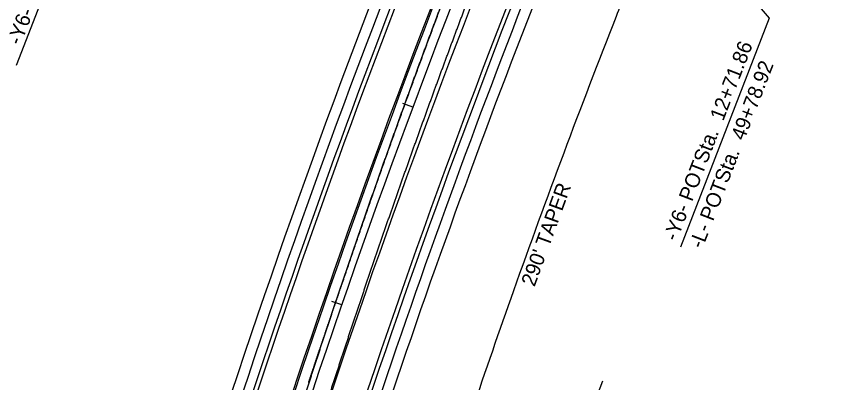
# Model space of a CAD drawing. Extents: x 1974386 to 1979988, y 776712 to 784860.
# Drawn here: x 1977461.3 to 1977853.8, y 781517 to 781691.1 of the extents above; entities that cross this region are included whole.
import ezdxf

# ---------------------------------------------------------------- set-up
doc = ezdxf.new("R2010")
doc.units = 0
for name, color, linetype in [('Prop Conc 2ft 6in Curb and Gutter', 7, 'Continuous'), ('Prop Conc 4in Sidewalk', 7, 'Continuous'), ('Prop Conc 5in Monolithic Keyed In Island', 7, 'Continuous'), ('Prop Dimension', 7, 'Continuous'), ('Prop EOT', 7, 'Continuous'), ('Prop Horizontal Alignment', 7, 'Continuous'), ('Prop Horizontal Alignment Station Label', 7, 'Continuous'), ('Prop Horizontal Alignment Tick Small', 7, 'Continuous'), ('Prop Lane Lines', 7, 'Continuous')]:
    doc.layers.add(name, color=color, linetype=linetype)

msp = doc.modelspace()

# ---------------------------------------------------------------- linework, layer by layer
at = {"layer": 'Prop Conc 2ft 6in Curb and Gutter'}
for radius, start, end in [(4173.25, 154.30709, 162.22085), (4226.75, 157.96844, 161.65559)]:
    msp.add_arc((1981585.24, 780180.82), radius, start, end, dxfattribs=at)
at = {"layer": 'Prop Conc 4in Sidewalk'}
for radius, start in [(4168.75, 156.07574), (4163.75, 156.07574), (4236.25, 157.96844), (4231.25, 157.97234)]:
    msp.add_arc((1981585.24, 780180.82), radius, start, 162.22085, dxfattribs=at)
at = {"layer": 'Prop Conc 5in Monolithic Keyed In Island'}
msp.add_arc((1981585.24, 780180.82), 4208, 157.44193, 162.14647, dxfattribs=at)
for points in [[(1977681.22, 781743.09), (1977680.6, 781741.49), (1977680.29, 781740.69), (1977679.98, 781739.89), (1977679.67, 781739.09), (1977679.36, 781738.29), (1977679.05, 781737.49), (1977678.74, 781736.7), (1977678.43, 781735.9), (1977678.12, 781735.1), (1977677.81, 781734.3), (1977677.5, 781733.5), (1977677.19, 781732.7), (1977676.88, 781731.9), (1977676.58, 781731.1), (1977676.27, 781730.3), (1977675.96, 781729.5), (1977675.65, 781728.7), (1977675.34, 781727.9), (1977675.04, 781727.1), (1977674.73, 781726.3), (1977674.42, 781725.5), (1977674.11, 781724.7), (1977673.81, 781723.9), (1977673.5, 781723.1), (1977673.19, 781722.3), (1977672.89, 781721.5), (1977672.58, 781720.7), (1977672.28, 781719.9), (1977671.97, 781719.1), (1977671.66, 781718.3), (1977671.36, 781717.5), (1977671.05, 781716.7), (1977670.75, 781715.9), (1977670.44, 781715.1), (1977670.14, 781714.3), (1977669.83, 781713.5), (1977669.53, 781712.7), (1977669.22, 781711.9), (1977668.92, 781711.09), (1977668.61, 781710.29), (1977668.31, 781709.49), (1977668.01, 781708.69), (1977667.7, 781707.89), (1977667.4, 781707.09), (1977667.1, 781706.29), (1977666.79, 781705.49), (1977666.49, 781704.68), (1977666.19, 781703.88), (1977665.88, 781703.08), (1977665.58, 781702.28), (1977665.28, 781701.48), (1977664.98, 781700.68), (1977664.67, 781699.87), (1977664.37, 781699.07), (1977664.07, 781698.27), (1977663.77, 781697.47), (1977663.47, 781696.67), (1977663.17, 781695.86), (1977662.87, 781695.06), (1977662.56, 781694.26), (1977662.26, 781693.46), (1977661.96, 781692.66), (1977661.66, 781691.85), (1977661.36, 781691.05), (1977661.06, 781690.25), (1977660.76, 781689.45), (1977660.46, 781688.64), (1977660.16, 781687.84), (1977659.86, 781687.04), (1977659.56, 781686.23), (1977659.27, 781685.43), (1977658.97, 781684.63), (1977658.67, 781683.83)], [(1977658.67, 781683.83), (1977658.37, 781683.02), (1977658.07, 781682.22), (1977657.77, 781681.42), (1977657.47, 781680.61), (1977657.18, 781679.81), (1977656.88, 781679.01), (1977656.58, 781678.2), (1977656.28, 781677.4), (1977655.99, 781676.6), (1977655.69, 781675.79), (1977655.39, 781674.99), (1977655.1, 781674.19), (1977654.8, 781673.38), (1977654.5, 781672.58), (1977654.21, 781671.77), (1977653.91, 781670.97), (1977653.61, 781670.17), (1977653.32, 781669.36), (1977653.02, 781668.56), (1977652.73, 781667.75), (1977652.43, 781666.95), (1977652.14, 781666.14), (1977651.84, 781665.34), (1977651.55, 781664.54), (1977651.25, 781663.73), (1977650.96, 781662.93), (1977650.66, 781662.12), (1977650.37, 781661.32), (1977650.07, 781660.51), (1977649.78, 781659.71), (1977649.49, 781658.9), (1977649.19, 781658.1), (1977648.9, 781657.29), (1977648.61, 781656.49), (1977648.31, 781655.68), (1977648.02, 781654.88), (1977647.73, 781654.07), (1977647.44, 781653.27), (1977647.14, 781652.46), (1977646.85, 781651.66), (1977646.56, 781650.85), (1977646.27, 781650.05), (1977645.98, 781649.24), (1977645.68, 781648.44), (1977645.39, 781647.63), (1977645.1, 781646.82), (1977644.81, 781646.02), (1977644.52, 781645.21), (1977644.23, 781644.41), (1977643.94, 781643.6), (1977643.65, 781642.79), (1977643.36, 781641.99), (1977643.07, 781641.18), (1977642.78, 781640.38), (1977642.49, 781639.57), (1977642.2, 781638.76), (1977641.91, 781637.96), (1977641.62, 781637.15), (1977641.33, 781636.34), (1977641.04, 781635.54), (1977640.75, 781634.73), (1977640.46, 781633.92), (1977640.18, 781633.12), (1977639.89, 781632.31), (1977639.6, 781631.5), (1977639.31, 781630.7), (1977639.02, 781629.89), (1977638.74, 781629.08), (1977638.45, 781628.28), (1977638.16, 781627.47), (1977637.88, 781626.66), (1977637.59, 781625.86), (1977637.3, 781625.05), (1977637.01, 781624.24)], [(1977637.01, 781624.24), (1977636.73, 781623.43), (1977636.44, 781622.63), (1977636.16, 781621.82), (1977635.87, 781621.01), (1977635.58, 781620.2), (1977635.3, 781619.4), (1977635.01, 781618.59), (1977634.73, 781617.78), (1977634.44, 781616.97), (1977634.16, 781616.16), (1977633.87, 781615.36), (1977633.59, 781614.55), (1977633.3, 781613.74), (1977633.02, 781612.93), (1977632.74, 781612.12), (1977632.45, 781611.32), (1977632.17, 781610.51), (1977631.88, 781609.7), (1977631.6, 781608.89), (1977631.32, 781608.08), (1977631.03, 781607.27), (1977630.75, 781606.47), (1977630.47, 781605.66), (1977630.19, 781604.85), (1977629.9, 781604.04), (1977629.62, 781603.23), (1977629.34, 781602.42), (1977629.06, 781601.61), (1977628.78, 781600.8), (1977628.49, 781600), (1977628.21, 781599.19), (1977627.93, 781598.38), (1977627.65, 781597.57), (1977627.37, 781596.76), (1977627.09, 781595.95), (1977626.81, 781595.14), (1977626.53, 781594.33), (1977626.25, 781593.52), (1977625.97, 781592.71), (1977625.69, 781591.9), (1977625.41, 781591.09), (1977625.13, 781590.28), (1977624.85, 781589.47), (1977624.57, 781588.66), (1977624.29, 781587.85), (1977624.01, 781587.04), (1977623.73, 781586.23), (1977623.45, 781585.42), (1977623.17, 781584.61), (1977622.9, 781583.8), (1977622.62, 781582.99), (1977622.34, 781582.18), (1977622.06, 781581.37), (1977621.78, 781580.56), (1977621.51, 781579.75), (1977621.23, 781578.94), (1977620.95, 781578.13), (1977620.68, 781577.32), (1977620.4, 781576.51), (1977620.12, 781575.7), (1977619.85, 781574.89), (1977619.57, 781574.08), (1977619.29, 781573.27), (1977619.02, 781572.46), (1977618.74, 781571.65), (1977618.47, 781570.83), (1977618.19, 781570.02), (1977617.91, 781569.21), (1977617.64, 781568.4), (1977617.36, 781567.59), (1977617.09, 781566.78), (1977616.81, 781565.97), (1977616.54, 781565.16), (1977616.27, 781564.34)], [(1977616.27, 781564.34), (1977615.82, 781563.07), (1977615.6, 781562.43), (1977615.38, 781561.79), (1977615.16, 781561.15), (1977614.94, 781560.51), (1977614.72, 781559.87), (1977614.5, 781559.23), (1977614.28, 781558.59), (1977614.06, 781557.95), (1977613.84, 781557.31), (1977613.62, 781556.67), (1977613.4, 781556.04), (1977613.18, 781555.4), (1977612.96, 781554.76), (1977612.74, 781554.12), (1977612.52, 781553.48), (1977612.3, 781552.84), (1977612.08, 781552.2), (1977611.86, 781551.56), (1977611.64, 781550.92), (1977611.42, 781550.28), (1977611.2, 781549.64), (1977610.98, 781549), (1977610.77, 781548.36), (1977610.55, 781547.72), (1977610.33, 781547.08), (1977610.11, 781546.44), (1977609.89, 781545.8), (1977609.67, 781545.16), (1977609.45, 781544.52), (1977609.24, 781543.88), (1977609.02, 781543.24), (1977608.8, 781542.6), (1977608.58, 781541.96), (1977608.37, 781541.32), (1977608.15, 781540.68), (1977607.93, 781540.04), (1977607.71, 781539.4), (1977607.5, 781538.76), (1977607.28, 781538.12), (1977607.06, 781537.48), (1977606.84, 781536.84), (1977606.63, 781536.2), (1977606.41, 781535.56), (1977606.19, 781534.92), (1977605.98, 781534.28), (1977605.76, 781533.63), (1977605.55, 781532.99), (1977605.33, 781532.35), (1977605.11, 781531.71), (1977604.9, 781531.07), (1977604.68, 781530.43), (1977604.47, 781529.79), (1977604.25, 781529.15), (1977604.03, 781528.51), (1977603.82, 781527.87), (1977603.6, 781527.23), (1977603.39, 781526.59), (1977603.17, 781525.94), (1977602.96, 781525.3), (1977602.74, 781524.66), (1977602.53, 781524.02), (1977602.31, 781523.38), (1977602.1, 781522.74), (1977601.88, 781522.1), (1977601.67, 781521.46), (1977601.45, 781520.82), (1977601.24, 781520.17), (1977601.03, 781519.53), (1977600.81, 781518.89), (1977600.6, 781518.25), (1977600.38, 781517.61), (1977600.17, 781516.97)]]:
    msp.add_spline(points, degree=3, dxfattribs=at)
at = {"layer": 'Prop Dimension'}
for centre, radius, start, end in [((1982594.42, 779780.37), 5210.83, 158.22493, 158.48863), ((1981701.08, 780137.49), 4248.77, 158.5515, 160.43084), ((1981585.24, 780180.82), 4125.1, 160.45901, 162.14498)]:
    msp.add_arc(centre, radius, start, end, dxfattribs=at)
at = {"layer": 'Prop EOT'}
for centre, radius, start, end in [((1981585.79, 780180.59), 4175.85, 153.34433, 162.22022), ((1981585.24, 780180.82), 4208.75, 157.44193, 162.22085), ((1981585.24, 780180.82), 4224.75, 157.96844, 161.65559)]:
    msp.add_arc(centre, radius, start, end, dxfattribs=at)
for points in [[(1977655.48, 781675.22), (1977655.82, 781676.14), (1977656.16, 781677.06), (1977656.5, 781677.98), (1977656.84, 781678.9), (1977657.18, 781679.82), (1977657.52, 781680.74), (1977657.86, 781681.66), (1977658.2, 781682.58), (1977658.55, 781683.5), (1977658.89, 781684.42), (1977659.23, 781685.34), (1977659.57, 781686.26), (1977659.92, 781687.17), (1977660.26, 781688.09), (1977660.6, 781689.01), (1977660.94, 781689.93), (1977661.29, 781690.85), (1977661.63, 781691.77), (1977661.98, 781692.69), (1977662.32, 781693.61), (1977662.66, 781694.52), (1977663.01, 781695.44), (1977663.35, 781696.36), (1977663.7, 781697.28), (1977664.04, 781698.2), (1977664.39, 781699.11), (1977664.73, 781700.03), (1977665.08, 781700.95), (1977665.43, 781701.87), (1977665.77, 781702.79), (1977666.12, 781703.7), (1977666.47, 781704.62), (1977666.81, 781705.54), (1977667.16, 781706.46), (1977667.51, 781707.37), (1977667.85, 781708.29), (1977668.2, 781709.21), (1977668.55, 781710.12), (1977668.9, 781711.04), (1977669.25, 781711.96), (1977669.6, 781712.88), (1977669.94, 781713.79), (1977670.29, 781714.71), (1977670.64, 781715.63), (1977670.99, 781716.54), (1977671.34, 781717.46), (1977671.69, 781718.37), (1977672.04, 781719.29), (1977672.39, 781720.21), (1977672.74, 781721.12), (1977673.09, 781722.04), (1977673.44, 781722.96), (1977673.8, 781723.87), (1977674.15, 781724.79), (1977674.5, 781725.7), (1977674.85, 781726.62), (1977675.2, 781727.53), (1977675.55, 781728.45), (1977675.91, 781729.36), (1977676.26, 781730.28), (1977676.61, 781731.2), (1977676.97, 781732.11), (1977677.32, 781733.03), (1977677.67, 781733.94), (1977678.03, 781734.86), (1977678.38, 781735.77), (1977678.73, 781736.68), (1977679.09, 781737.6), (1977679.44, 781738.51), (1977679.8, 781739.43), (1977680.15, 781740.34), (1977680.51, 781741.26), (1977681.22, 781743.09)], [(1977630.92, 781606.93), (1977631.24, 781607.86), (1977631.56, 781608.78), (1977631.89, 781609.71), (1977632.21, 781610.64), (1977632.54, 781611.56), (1977632.86, 781612.49), (1977633.19, 781613.41), (1977633.51, 781614.34), (1977633.84, 781615.26), (1977634.17, 781616.19), (1977634.49, 781617.11), (1977634.82, 781618.04), (1977635.14, 781618.96), (1977635.47, 781619.88), (1977635.8, 781620.81), (1977636.13, 781621.73), (1977636.45, 781622.66), (1977636.78, 781623.58), (1977637.11, 781624.51), (1977637.44, 781625.43), (1977637.77, 781626.35), (1977638.09, 781627.28), (1977638.42, 781628.2), (1977638.75, 781629.13), (1977639.08, 781630.05), (1977639.41, 781630.97), (1977639.74, 781631.9), (1977640.07, 781632.82), (1977640.4, 781633.74), (1977640.73, 781634.67), (1977641.06, 781635.59), (1977641.39, 781636.51), (1977641.72, 781637.44), (1977642.05, 781638.36), (1977642.39, 781639.28), (1977642.72, 781640.21), (1977643.05, 781641.13), (1977643.38, 781642.05), (1977643.71, 781642.97), (1977644.05, 781643.9), (1977644.38, 781644.82), (1977644.71, 781645.74), (1977645.04, 781646.66), (1977645.38, 781647.59), (1977645.71, 781648.51), (1977646.05, 781649.43), (1977646.38, 781650.35), (1977646.71, 781651.28), (1977647.05, 781652.2), (1977647.38, 781653.12), (1977647.72, 781654.04), (1977648.05, 781654.96), (1977648.39, 781655.88), (1977648.72, 781656.81), (1977649.06, 781657.73), (1977649.39, 781658.65), (1977649.73, 781659.57), (1977650.07, 781660.49), (1977650.4, 781661.41), (1977650.74, 781662.33), (1977651.08, 781663.25), (1977651.41, 781664.18), (1977651.75, 781665.1), (1977652.09, 781666.02), (1977652.43, 781666.94), (1977652.77, 781667.86), (1977653.1, 781668.78), (1977653.44, 781669.7), (1977653.78, 781670.62), (1977654.12, 781671.54), (1977654.46, 781672.46), (1977654.8, 781673.38), (1977655.14, 781674.3), (1977655.48, 781675.22)], [(1977607.54, 781538.24), (1977607.85, 781539.17), (1977608.16, 781540.11), (1977608.46, 781541.04), (1977608.77, 781541.97), (1977609.08, 781542.9), (1977609.39, 781543.83), (1977609.7, 781544.76), (1977610.01, 781545.69), (1977610.32, 781546.62), (1977610.63, 781547.55), (1977610.94, 781548.48), (1977611.25, 781549.41), (1977611.56, 781550.34), (1977611.87, 781551.27), (1977612.18, 781552.2), (1977612.49, 781553.13), (1977612.8, 781554.06), (1977613.12, 781554.99), (1977613.43, 781555.92), (1977613.74, 781556.85), (1977614.05, 781557.78), (1977614.36, 781558.71), (1977614.68, 781559.64), (1977614.99, 781560.56), (1977615.3, 781561.49), (1977615.62, 781562.42), (1977615.93, 781563.35), (1977616.24, 781564.28), (1977616.56, 781565.21), (1977616.87, 781566.14), (1977617.19, 781567.07), (1977617.5, 781568), (1977617.82, 781568.92), (1977618.13, 781569.85), (1977618.45, 781570.78), (1977618.76, 781571.71), (1977619.08, 781572.64), (1977619.39, 781573.57), (1977619.71, 781574.49), (1977620.03, 781575.42), (1977620.34, 781576.35), (1977620.66, 781577.28), (1977620.98, 781578.21), (1977621.3, 781579.13), (1977621.61, 781580.06), (1977621.93, 781580.99), (1977622.25, 781581.92), (1977622.57, 781582.84), (1977622.88, 781583.77), (1977623.2, 781584.7), (1977623.52, 781585.63), (1977623.84, 781586.55), (1977624.16, 781587.48), (1977624.48, 781588.41), (1977624.8, 781589.33), (1977625.12, 781590.26), (1977625.44, 781591.19), (1977625.76, 781592.12), (1977626.08, 781593.04), (1977626.4, 781593.97), (1977626.72, 781594.9), (1977627.04, 781595.82), (1977627.37, 781596.75), (1977627.69, 781597.67), (1977628.01, 781598.6), (1977628.33, 781599.53), (1977628.65, 781600.45), (1977628.98, 781601.38), (1977629.3, 781602.3), (1977629.62, 781603.23), (1977629.94, 781604.16), (1977630.27, 781605.08), (1977630.59, 781606.01), (1977630.92, 781606.93)], [(1977585.36, 781469.17), (1977585.65, 781470.11), (1977585.94, 781471.04), (1977586.23, 781471.98), (1977586.52, 781472.91), (1977586.82, 781473.85), (1977587.11, 781474.79), (1977587.4, 781475.72), (1977587.7, 781476.66), (1977587.99, 781477.59), (1977588.28, 781478.53), (1977588.58, 781479.46), (1977588.87, 781480.4), (1977589.17, 781481.33), (1977589.46, 781482.27), (1977589.76, 781483.2), (1977590.05, 781484.14), (1977590.35, 781485.07), (1977590.64, 781486.01), (1977590.94, 781486.94), (1977591.23, 781487.88), (1977591.53, 781488.81), (1977591.83, 781489.74), (1977592.12, 781490.68), (1977592.42, 781491.61), (1977592.72, 781492.55), (1977593.01, 781493.48), (1977593.31, 781494.42), (1977593.61, 781495.35), (1977593.91, 781496.28), (1977594.2, 781497.22), (1977594.5, 781498.15), (1977594.8, 781499.09), (1977595.1, 781500.02), (1977595.4, 781500.95), (1977595.7, 781501.89), (1977596, 781502.82), (1977596.3, 781503.75), (1977596.6, 781504.69), (1977596.9, 781505.62), (1977597.2, 781506.55), (1977597.5, 781507.49), (1977597.8, 781508.42), (1977598.1, 781509.35), (1977598.4, 781510.29), (1977598.7, 781511.22), (1977599, 781512.15), (1977599.31, 781513.08), (1977599.61, 781514.02), (1977599.91, 781514.95), (1977600.21, 781515.88), (1977600.52, 781516.82), (1977600.82, 781517.75), (1977601.12, 781518.68), (1977601.43, 781519.61), (1977601.73, 781520.54), (1977602.03, 781521.48), (1977602.34, 781522.41), (1977602.64, 781523.34), (1977602.95, 781524.27), (1977603.25, 781525.2), (1977603.56, 781526.14), (1977603.86, 781527.07), (1977604.17, 781528), (1977604.47, 781528.93), (1977604.78, 781529.86), (1977605.08, 781530.79), (1977605.39, 781531.73), (1977605.7, 781532.66), (1977606, 781533.59), (1977606.31, 781534.52), (1977606.62, 781535.45), (1977606.92, 781536.38), (1977607.23, 781537.31), (1977607.54, 781538.24)]]:
    msp.add_spline(points, degree=3, dxfattribs=at)
at = {"layer": 'Prop Horizontal Alignment'}
msp.add_arc((1981585.24, 780180.82), 4200, 153.11985, 162.22085, dxfattribs=at)
at = {"layer": 'Prop Horizontal Alignment Station Label'}
for p, q in [((1977716.83, 781813.07), (1977819.32, 781690.28)), ((1977461.4, 781667.9), (1977502.75, 781775.73)), ((1977819.32, 781690.28), (1977777.24, 781581.35)), ((1977702.77, 781420.6), (1977740.26, 781517.77))]:
    msp.add_line(p, q, dxfattribs=at)
at = {"layer": 'Prop Horizontal Alignment Tick Small'}
for p, q in [((1977649.82, 781647.95), (1977645.13, 781649.7)), ((1977616.01, 781553.85), (1977611.28, 781555.48))]:
    msp.add_line(p, q, dxfattribs=at)
at = {"layer": 'Prop Lane Lines'}
msp.add_arc((1981585.24, 780180.82), 4191.25, 158.03179, 162.22085, dxfattribs=at)
for points in [[(1977665.76, 781671.31), (1977666.1, 781672.23), (1977666.44, 781673.15), (1977666.78, 781674.06), (1977667.12, 781674.98), (1977667.46, 781675.9), (1977667.8, 781676.82), (1977668.14, 781677.73), (1977668.48, 781678.65), (1977668.82, 781679.57), (1977669.16, 781680.48), (1977669.5, 781681.4), (1977669.84, 781682.32), (1977670.19, 781683.23), (1977670.53, 781684.15), (1977670.87, 781685.07), (1977671.21, 781685.98), (1977671.55, 781686.9), (1977671.9, 781687.82), (1977672.24, 781688.73), (1977672.58, 781689.65), (1977672.93, 781690.56), (1977673.27, 781691.48), (1977673.61, 781692.4), (1977673.96, 781693.31), (1977674.3, 781694.23), (1977674.65, 781695.14), (1977674.99, 781696.06), (1977675.34, 781696.97), (1977675.68, 781697.89), (1977676.03, 781698.8), (1977676.37, 781699.72), (1977676.72, 781700.63), (1977677.06, 781701.55), (1977677.41, 781702.46), (1977677.76, 781703.38), (1977678.1, 781704.29), (1977678.45, 781705.21), (1977678.8, 781706.12), (1977679.14, 781707.04), (1977679.49, 781707.95), (1977679.84, 781708.87), (1977680.19, 781709.78), (1977680.54, 781710.7), (1977680.88, 781711.61), (1977681.23, 781712.52), (1977681.58, 781713.44), (1977681.93, 781714.35), (1977682.28, 781715.27), (1977682.63, 781716.18), (1977682.98, 781717.09), (1977683.33, 781718.01), (1977683.68, 781718.92), (1977684.03, 781719.83), (1977684.38, 781720.75), (1977684.73, 781721.66), (1977685.08, 781722.57), (1977685.43, 781723.49), (1977685.78, 781724.4), (1977686.13, 781725.31), (1977686.49, 781726.23), (1977686.84, 781727.14), (1977687.19, 781728.05), (1977687.54, 781728.96), (1977687.9, 781729.88), (1977688.25, 781730.79), (1977688.6, 781731.7), (1977688.95, 781732.61), (1977689.31, 781733.53), (1977689.66, 781734.44), (1977690.02, 781735.35), (1977690.37, 781736.26), (1977690.72, 781737.18), (1977691.43, 781739)], [(1977641.26, 781603.2), (1977641.59, 781604.13), (1977641.91, 781605.05), (1977642.23, 781605.97), (1977642.56, 781606.89), (1977642.88, 781607.82), (1977643.21, 781608.74), (1977643.53, 781609.66), (1977643.85, 781610.58), (1977644.18, 781611.51), (1977644.5, 781612.43), (1977644.83, 781613.35), (1977645.16, 781614.27), (1977645.48, 781615.2), (1977645.81, 781616.12), (1977646.13, 781617.04), (1977646.46, 781617.96), (1977646.79, 781618.88), (1977647.11, 781619.81), (1977647.44, 781620.73), (1977647.77, 781621.65), (1977648.09, 781622.57), (1977648.42, 781623.49), (1977648.75, 781624.42), (1977649.08, 781625.34), (1977649.41, 781626.26), (1977649.74, 781627.18), (1977650.06, 781628.1), (1977650.39, 781629.02), (1977650.72, 781629.94), (1977651.05, 781630.86), (1977651.38, 781631.78), (1977651.71, 781632.71), (1977652.04, 781633.63), (1977652.37, 781634.55), (1977652.7, 781635.47), (1977653.03, 781636.39), (1977653.36, 781637.31), (1977653.7, 781638.23), (1977654.03, 781639.15), (1977654.36, 781640.07), (1977654.69, 781640.99), (1977655.02, 781641.91), (1977655.35, 781642.83), (1977655.69, 781643.75), (1977656.02, 781644.67), (1977656.35, 781645.59), (1977656.69, 781646.51), (1977657.02, 781647.43), (1977657.35, 781648.35), (1977657.69, 781649.27), (1977658.02, 781650.19), (1977658.35, 781651.11), (1977658.69, 781652.03), (1977659.02, 781652.94), (1977659.36, 781653.86), (1977659.69, 781654.78), (1977660.03, 781655.7), (1977660.36, 781656.62), (1977660.7, 781657.54), (1977661.03, 781658.46), (1977661.37, 781659.38), (1977661.71, 781660.29), (1977662.04, 781661.21), (1977662.38, 781662.13), (1977662.72, 781663.05), (1977663.05, 781663.97), (1977663.39, 781664.89), (1977663.73, 781665.8), (1977664.07, 781666.72), (1977664.41, 781667.64), (1977664.74, 781668.56), (1977665.08, 781669.48), (1977665.42, 781670.39), (1977665.76, 781671.31)], [(1977617.95, 781534.69), (1977618.26, 781535.62), (1977618.56, 781536.55), (1977618.87, 781537.48), (1977619.18, 781538.4), (1977619.49, 781539.33), (1977619.8, 781540.26), (1977620.1, 781541.19), (1977620.41, 781542.12), (1977620.72, 781543.04), (1977621.03, 781543.97), (1977621.34, 781544.9), (1977621.65, 781545.83), (1977621.96, 781546.75), (1977622.27, 781547.68), (1977622.58, 781548.61), (1977622.89, 781549.54), (1977623.2, 781550.46), (1977623.51, 781551.39), (1977623.82, 781552.32), (1977624.13, 781553.25), (1977624.44, 781554.17), (1977624.76, 781555.1), (1977625.07, 781556.03), (1977625.38, 781556.95), (1977625.69, 781557.88), (1977626.01, 781558.81), (1977626.32, 781559.73), (1977626.63, 781560.66), (1977626.94, 781561.59), (1977627.26, 781562.51), (1977627.57, 781563.44), (1977627.89, 781564.37), (1977628.2, 781565.29), (1977628.51, 781566.22), (1977628.83, 781567.14), (1977629.14, 781568.07), (1977629.46, 781569), (1977629.77, 781569.92), (1977630.09, 781570.85), (1977630.4, 781571.77), (1977630.72, 781572.7), (1977631.04, 781573.62), (1977631.35, 781574.55), (1977631.67, 781575.47), (1977631.99, 781576.4), (1977632.3, 781577.32), (1977632.62, 781578.25), (1977632.94, 781579.18), (1977633.25, 781580.1), (1977633.57, 781581.03), (1977633.89, 781581.95), (1977634.21, 781582.87), (1977634.53, 781583.8), (1977634.85, 781584.72), (1977635.16, 781585.65), (1977635.48, 781586.57), (1977635.8, 781587.5), (1977636.12, 781588.42), (1977636.44, 781589.35), (1977636.76, 781590.27), (1977637.08, 781591.19), (1977637.4, 781592.12), (1977637.72, 781593.04), (1977638.04, 781593.97), (1977638.36, 781594.89), (1977638.69, 781595.81), (1977639.01, 781596.74), (1977639.33, 781597.66), (1977639.65, 781598.59), (1977639.97, 781599.51), (1977640.29, 781600.43), (1977640.62, 781601.36), (1977640.94, 781602.28), (1977641.26, 781603.2)], [(1977595.83, 781465.8), (1977596.12, 781466.73), (1977596.41, 781467.67), (1977596.7, 781468.6), (1977596.99, 781469.53), (1977597.28, 781470.47), (1977597.58, 781471.4), (1977597.87, 781472.33), (1977598.16, 781473.26), (1977598.45, 781474.2), (1977598.75, 781475.13), (1977599.04, 781476.06), (1977599.33, 781477), (1977599.63, 781477.93), (1977599.92, 781478.86), (1977600.21, 781479.79), (1977600.51, 781480.73), (1977600.8, 781481.66), (1977601.1, 781482.59), (1977601.39, 781483.52), (1977601.69, 781484.45), (1977601.98, 781485.39), (1977602.28, 781486.32), (1977602.57, 781487.25), (1977602.87, 781488.18), (1977603.17, 781489.11), (1977603.46, 781490.05), (1977603.76, 781490.98), (1977604.06, 781491.91), (1977604.35, 781492.84), (1977604.65, 781493.77), (1977604.95, 781494.7), (1977605.25, 781495.64), (1977605.54, 781496.57), (1977605.84, 781497.5), (1977606.14, 781498.43), (1977606.44, 781499.36), (1977606.74, 781500.29), (1977607.04, 781501.22), (1977607.34, 781502.15), (1977607.64, 781503.08), (1977607.94, 781504.01), (1977608.24, 781504.95), (1977608.54, 781505.88), (1977608.84, 781506.81), (1977609.14, 781507.74), (1977609.44, 781508.67), (1977609.74, 781509.6), (1977610.04, 781510.53), (1977610.34, 781511.46), (1977610.64, 781512.39), (1977610.95, 781513.32), (1977611.25, 781514.25), (1977611.55, 781515.18), (1977611.85, 781516.11), (1977612.16, 781517.04), (1977612.46, 781517.97), (1977612.76, 781518.9), (1977613.06, 781519.83), (1977613.37, 781520.76), (1977613.67, 781521.69), (1977613.98, 781522.62), (1977614.28, 781523.54), (1977614.59, 781524.47), (1977614.89, 781525.4), (1977615.2, 781526.33), (1977615.5, 781527.26), (1977615.81, 781528.19), (1977616.11, 781529.12), (1977616.42, 781530.05), (1977616.72, 781530.98), (1977617.03, 781531.91), (1977617.34, 781532.83), (1977617.64, 781533.76), (1977617.95, 781534.69)]]:
    msp.add_spline(points, degree=3, dxfattribs=at)

# ---------------------------------------------------------------- texts
at = {"layer": 'Prop Dimension'}
msp.add_text("290' TAPER", height=7, rotation=70.0233, dxfattribs=at).set_placement((1977707.75, 781562.22))
at = {"layer": 'Prop Horizontal Alignment Station Label'}
for s, p in [('-Y6- PCSta.  10+92.95', (1977463.22, 781677.06)), ('-Y6- POTSta.  12+71.86', (1977775.36, 781583.78)), ('-L- POTSta.  49+78.92', (1977787.59, 781580.27))]:
    msp.add_text(s, height=7, rotation=68.8775, dxfattribs=at).set_placement(p)

doc.saveas('drawing.dxf')
